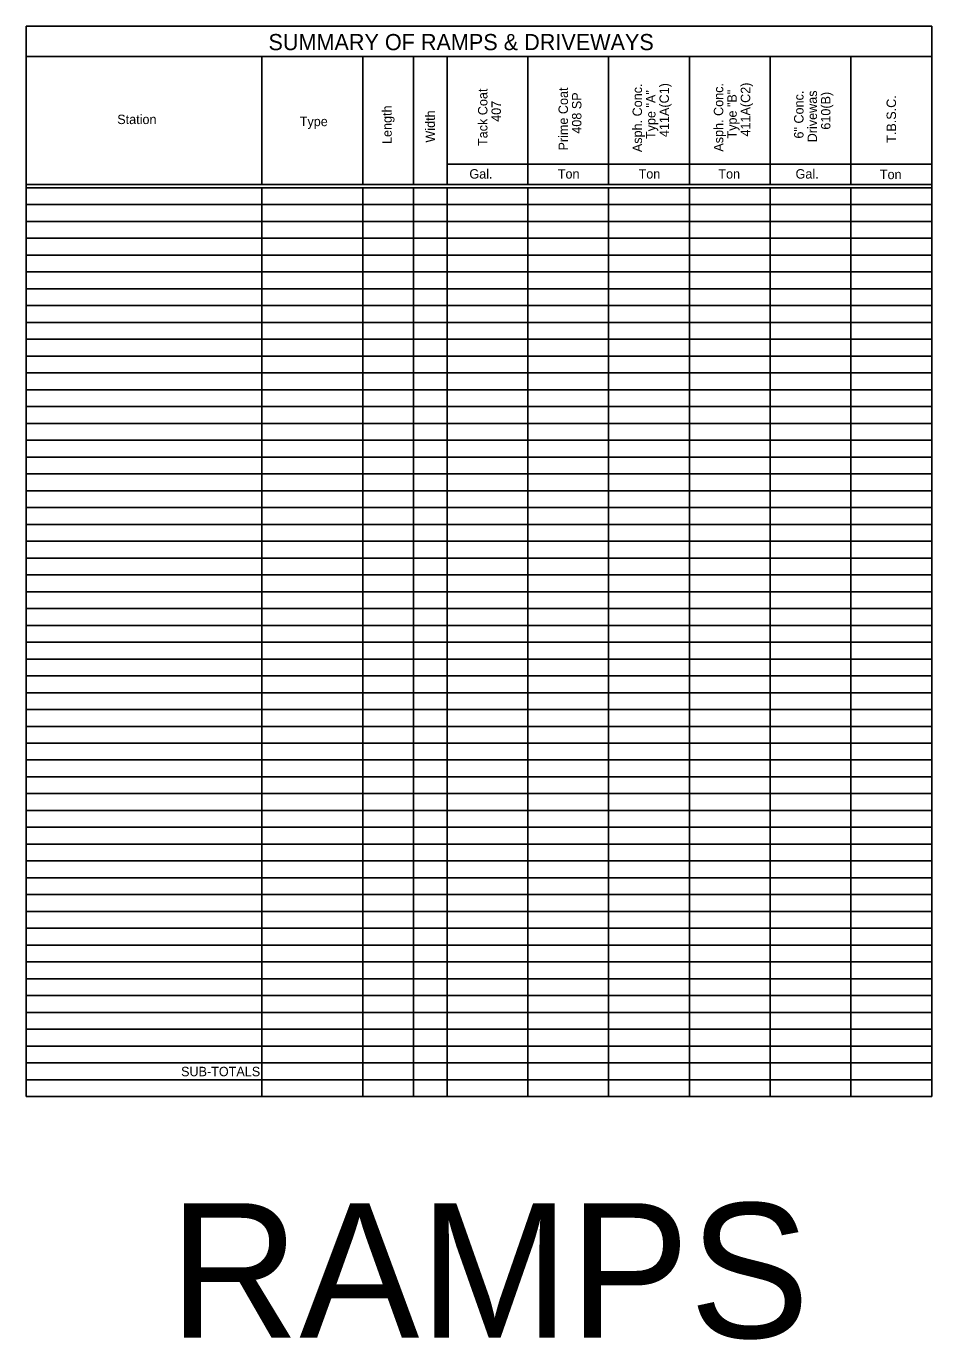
# Model space of a CAD drawing. Extents: x 1790274 to 1791453, y 1790011 to 1790884.
# Drawn here: x 1790885.1 to 1791019.6, y 1790688.5 to 1790883.6 of the extents above; entities that cross this region are included whole.
import ezdxf

# ---------------------------------------------------------------- set-up
doc = ezdxf.new("R2010")
doc.units = 0
doc.layers.add('Level 1', color=7, linetype='Continuous')
doc.layers.add('Level 2', color=7, linetype='Continuous')

msp = doc.modelspace()

# ---------------------------------------------------------------- linework, layer by layer
at = {"layer": 'Level 1'}
for p, q in [((1790885.1, 1790883.64), (1791019.6, 1790883.64)), ((1790885.1, 1790724.64), (1790885.1, 1790883.64)), ((1791019.6, 1790724.64), (1791019.6, 1790883.64)), ((1790885.1, 1790879.14), (1791019.6, 1790879.14)), ((1790920.1, 1790860.14), (1790920.1, 1790879.14)), ((1790935.1, 1790860.14), (1790935.1, 1790879.14)), ((1790942.6, 1790860.14), (1790942.6, 1790879.14)), ((1790947.6, 1790860.14), (1790947.6, 1790879.14)), ((1790959.6, 1790860.14), (1790959.6, 1790879.14)), ((1790971.6, 1790860.14), (1790971.6, 1790879.14)), ((1790983.6, 1790860.14), (1790983.6, 1790879.14)), ((1790995.6, 1790860.14), (1790995.6, 1790879.14)), ((1791007.6, 1790860.14), (1791007.6, 1790879.14)), ((1790947.6, 1790863.14), (1791019.6, 1790863.14)), ((1790885.1, 1790860.14), (1791019.6, 1790860.14)), ((1790885.1, 1790859.64), (1791019.6, 1790859.64)), ((1790920.1, 1790724.64), (1790920.1, 1790859.64)), ((1790935.1, 1790724.64), (1790935.1, 1790859.64)), ((1790942.6, 1790724.64), (1790942.6, 1790859.64)), ((1790947.6, 1790724.64), (1790947.6, 1790859.64)), ((1790959.6, 1790724.64), (1790959.6, 1790859.64)), ((1790971.6, 1790724.64), (1790971.6, 1790859.64)), ((1790983.6, 1790724.64), (1790983.6, 1790859.64)), ((1790995.6, 1790724.64), (1790995.6, 1790859.64)), ((1791007.6, 1790724.64), (1791007.6, 1790859.64)), ((1790885.1, 1790857.14), (1791019.6, 1790857.14)), ((1790885.1, 1790854.64), (1791019.6, 1790854.64)), ((1790885.1, 1790852.14), (1791019.6, 1790852.14)), ((1790885.1, 1790849.64), (1791019.6, 1790849.64)), ((1790885.1, 1790847.14), (1791019.6, 1790847.14)), ((1790885.1, 1790844.64), (1791019.6, 1790844.64)), ((1790885.1, 1790842.14), (1791019.6, 1790842.14)), ((1790885.1, 1790839.64), (1791019.6, 1790839.64)), ((1790885.1, 1790837.14), (1791019.6, 1790837.14)), ((1790885.1, 1790834.64), (1791019.6, 1790834.64)), ((1790885.1, 1790832.14), (1791019.6, 1790832.14)), ((1790885.1, 1790829.64), (1791019.6, 1790829.64)), ((1790885.1, 1790827.14), (1791019.6, 1790827.14)), ((1790885.1, 1790824.64), (1791019.6, 1790824.64)), ((1790885.1, 1790822.14), (1791019.6, 1790822.14)), ((1790885.1, 1790819.64), (1791019.6, 1790819.64)), ((1790885.1, 1790817.14), (1791019.6, 1790817.14)), ((1790885.1, 1790814.64), (1791019.6, 1790814.64)), ((1790885.1, 1790812.14), (1791019.6, 1790812.14)), ((1790885.1, 1790809.64), (1791019.6, 1790809.64)), ((1790885.1, 1790807.14), (1791019.6, 1790807.14)), ((1790885.1, 1790804.64), (1791019.6, 1790804.64)), ((1790885.1, 1790802.14), (1791019.6, 1790802.14)), ((1790885.1, 1790799.64), (1791019.6, 1790799.64)), ((1790885.1, 1790797.14), (1791019.6, 1790797.14)), ((1790885.1, 1790794.64), (1791019.6, 1790794.64)), ((1790885.1, 1790792.14), (1791019.6, 1790792.14)), ((1790885.1, 1790789.64), (1791019.6, 1790789.64)), ((1790885.1, 1790787.14), (1791019.6, 1790787.14)), ((1790885.1, 1790784.64), (1791019.6, 1790784.64)), ((1790885.1, 1790782.14), (1791019.6, 1790782.14)), ((1790885.1, 1790779.64), (1791019.6, 1790779.64)), ((1790885.1, 1790777.14), (1791019.6, 1790777.14)), ((1790885.1, 1790774.64), (1791019.6, 1790774.64)), ((1790885.1, 1790772.14), (1791019.6, 1790772.14)), ((1790885.1, 1790769.64), (1791019.6, 1790769.64)), ((1790885.1, 1790767.14), (1791019.6, 1790767.14)), ((1790885.1, 1790764.64), (1791019.6, 1790764.64)), ((1790885.1, 1790762.14), (1791019.6, 1790762.14)), ((1790885.1, 1790759.64), (1791019.6, 1790759.64)), ((1790885.1, 1790757.14), (1791019.6, 1790757.14)), ((1790885.1, 1790754.64), (1791019.6, 1790754.64)), ((1790885.1, 1790752.14), (1791019.6, 1790752.14)), ((1790885.1, 1790749.64), (1791019.6, 1790749.64)), ((1790885.1, 1790747.14), (1791019.6, 1790747.14)), ((1790885.1, 1790744.64), (1791019.6, 1790744.64)), ((1790885.1, 1790742.14), (1791019.6, 1790742.14)), ((1790885.1, 1790739.64), (1791019.6, 1790739.64)), ((1790885.1, 1790737.14), (1791019.6, 1790737.14)), ((1790885.1, 1790734.64), (1791019.6, 1790734.64)), ((1790885.1, 1790732.14), (1791019.6, 1790732.14)), ((1790885.1, 1790729.64), (1791019.6, 1790729.64)), ((1790885.1, 1790727.14), (1791019.6, 1790727.14)), ((1790885.1, 1790724.64), (1791019.6, 1790724.64))]:
    msp.add_line(p, q, dxfattribs=at)

# ---------------------------------------------------------------- texts
at = {"layer": 'Level 2'}
for s, height, p in [('SUMMARY OF RAMPS & DRIVEWAYS', 2.4, (1790921.07, 1790880.09)), ('Station', 1.4, (1790898.61, 1790869.11)), ('Type', 1.4, (1790925.72, 1790868.8)), ('Gal.', 1.4, (1790950.92, 1790861.01)), ('Ton', 1.4, (1790964.05, 1790861.01)), ('Ton', 1.4, (1790976.05, 1790861.01)), ('Ton', 1.4, (1790987.9, 1790861.01)), ('Gal.', 1.4, (1790999.37, 1790861.01)), ('Ton', 1.4, (1791011.89, 1790860.93)), ('SUB-TOTALS', 1.4, (1790908.09, 1790727.66)), ('RAMPS', 20, (1790906.34, 1790688.8))]:
    msp.add_text(s, height=height, dxfattribs=at).set_placement(p)
for s, p in [('Asph. Conc.', (1790976.56, 1790864.94)), ('411A(C1)', (1790980.56, 1790867.18)), ('Asph. Conc.', (1790988.63, 1790865.01)), ('411A(C2)', (1790992.63, 1790867.26)), ('Tack Coat', (1790953.6, 1790865.85)), ('Prime Coat', (1790965.56, 1790865.18)), ('408 SP', (1790967.56, 1790867.68)), ('Type "A"', (1790978.56, 1790866.88)), ('Type "B"', (1790990.63, 1790866.96)), ('6" Conc.', (1791000.55, 1790866.96)), ('Drivewas', (1791002.55, 1790866.4)), ('610(B)', (1791004.55, 1790868.28)), ('T.B.S.C.', (1791014.29, 1790866.32)), ('Length', (1790939.38, 1790866.15)), ('Width', (1790945.8, 1790866.36)), ('407', (1790955.6, 1790869.44))]:
    msp.add_text(s, height=1.4, rotation=90, dxfattribs=at).set_placement(p)

doc.saveas('drawing.dxf')
